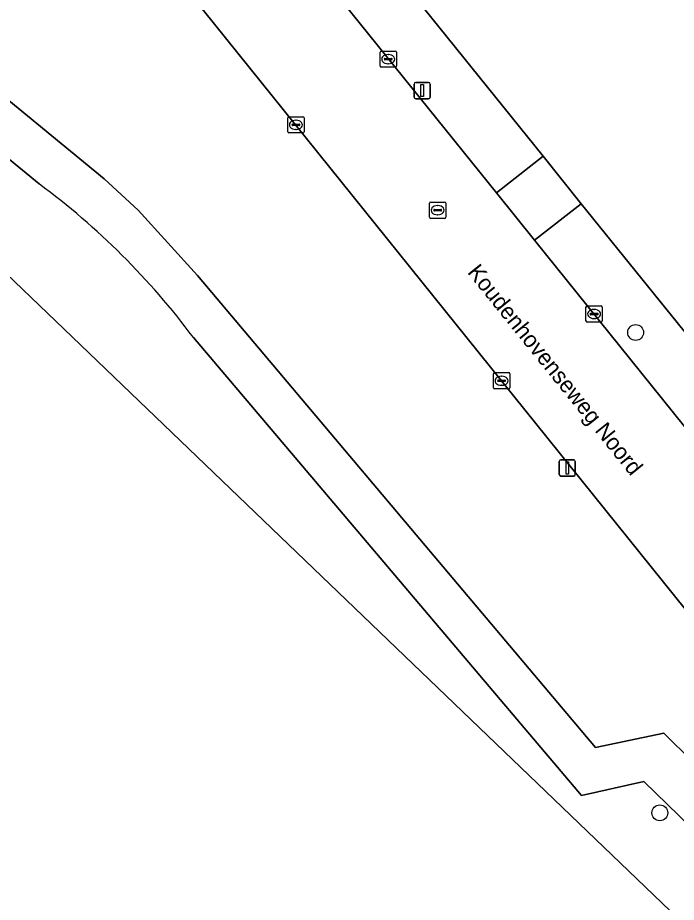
# Model space of a CAD drawing. Extents: x 162417 to 163722, y 384268 to 385417.
# Drawn here: x 163403.1 to 163443.6, y 384814.8 to 384869.2 of the extents above; entities that cross this region are included whole.
import ezdxf

# ---------------------------------------------------------------- set-up
doc = ezdxf.new("R2010")
doc.units = 0
for name, color, linetype in [('IMGEO_Berm_groen', 7, 'Continuous'), ('IMGEO_Boom', 7, 'Continuous'), ('IMGEO_Erf', 7, 'Continuous'), ('IMGEO_Kolk', 7, 'Continuous'), ('IMGEO_Lichtmast', 7, 'Continuous'), ('IMGEO_Loofbos', 7, 'Continuous'), ('IMGEO_Openbare_ruimte_label', 7, 'Continuous'), ('IMGEO_Rijbaan_lokaal_gesloten', 7, 'Continuous'), ('IMGEO_Rioolput', 7, 'Continuous'), ('IMGEO_Voetpad_open', 7, 'Continuous')]:
    doc.layers.add(name, color=color, linetype=linetype)

msp = doc.modelspace()

# ---------------------------------------------------------------- linework, layer by layer
at = {"layer": 'IMGEO_Berm_groen'}
for points in [[(163416.764, 384883.847), (163413.249, 384882.384), (163432.532, 384858.437), (163435.391, 384860.693)], [(163437.735, 384857.778), (163434.868, 384855.535), (163446.713, 384840.825), (163447.501, 384841.435), (163447.728, 384841.15), (163449.843, 384842.786), (163449.614, 384843.069)]]:
    msp.add_lwpolyline(points, close=True, dxfattribs=at)
at = {"layer": 'IMGEO_Boom'}
for centre in [(163441.083, 384849.86), (163442.567, 384820.322)]:
    msp.add_circle(centre, 0.489, dxfattribs=at)
at = {"layer": 'IMGEO_Erf'}
for points in [[(163565.372, 384794.06), (163550.928, 384821.281), (163500, 384915.752), (163498.731, 384918.106), (163416.764, 384883.847), (163435.391, 384860.693), (163437.735, 384857.778), (163449.614, 384843.069), (163449.843, 384842.786), (163451.746, 384840.437), (163452.011, 384840.109), (163461.716, 384828.124), (163463.926, 384825.396), (163473.971, 384812.925)], [(163478.968, 384778.944), (163452.807, 384811.328), (163449.552, 384814.496), (163444.744, 384812.832), (163371.736, 384882.911), (163368.168, 384880.503), (163366.653, 384879.471), (163363.837, 384877.552), (163359.249, 384874.08)]]:
    msp.add_lwpolyline(points, dxfattribs=at)
at = {"layer": 'IMGEO_Kolk'}
for p, q in [((163425.375, 384866.238), (163425.375, 384867.09)), ((163425.45, 384867.164), (163426.302, 384867.164)), ((163426.376, 384867.09), (163426.376, 384866.238)), ((163425.634, 384866.658), (163425.634, 384866.67)), ((163426.072, 384866.621), (163425.674, 384866.621)), ((163425.677, 384866.707), (163426.075, 384866.707)), ((163425.863, 384866.944), (163425.888, 384866.944)), ((163426.118, 384866.67), (163426.118, 384866.658)), ((163426.302, 384866.164), (163425.45, 384866.164)), ((163425.886, 384866.384), (163425.861, 384866.384)), ((163419.7, 384862.2), (163419.7, 384863.052)), ((163419.775, 384863.126), (163420.627, 384863.126)), ((163420.188, 384862.906), (163420.213, 384862.906)), ((163420.701, 384863.052), (163420.701, 384862.2)), ((163419.959, 384862.62), (163419.959, 384862.632)), ((163420.397, 384862.583), (163419.999, 384862.583)), ((163420.002, 384862.669), (163420.4, 384862.669)), ((163420.211, 384862.346), (163420.186, 384862.346)), ((163420.443, 384862.632), (163420.443, 384862.62)), ((163420.627, 384862.126), (163419.775, 384862.126)), ((163438.029, 384850.568), (163438.029, 384851.42)), ((163438.104, 384851.494), (163438.956, 384851.494)), ((163438.517, 384851.274), (163438.542, 384851.274)), ((163439.03, 384851.42), (163439.03, 384850.568)), ((163438.288, 384850.988), (163438.288, 384851)), ((163438.726, 384850.951), (163438.328, 384850.951)), ((163438.331, 384851.037), (163438.729, 384851.037)), ((163438.54, 384850.714), (163438.515, 384850.714)), ((163438.772, 384851), (163438.772, 384850.988)), ((163438.956, 384850.494), (163438.104, 384850.494)), ((163432.342, 384846.464), (163432.342, 384847.316)), ((163432.417, 384847.39), (163433.269, 384847.39)), ((163432.601, 384846.884), (163432.601, 384846.896)), ((163432.644, 384846.933), (163433.042, 384846.933)), ((163432.83, 384847.17), (163432.855, 384847.17)), ((163433.085, 384846.896), (163433.085, 384846.884)), ((163433.343, 384847.316), (163433.343, 384846.464)), ((163433.269, 384846.39), (163432.417, 384846.39)), ((163433.039, 384846.847), (163432.641, 384846.847)), ((163432.853, 384846.61), (163432.828, 384846.61))]:
    msp.add_line(p, q, dxfattribs=at)
for points in [[(163425.375, 384866.238), (163425.375, 384867.09)], [(163425.45, 384867.164), (163426.302, 384867.164)], [(163426.376, 384867.09), (163426.376, 384866.238)], [(163426.302, 384866.164), (163425.45, 384866.164)], [(163419.7, 384862.2), (163419.7, 384863.052)], [(163419.775, 384863.126), (163420.627, 384863.126)], [(163420.701, 384863.052), (163420.701, 384862.2)], [(163420.627, 384862.126), (163419.775, 384862.126)], [(163438.029, 384850.568), (163438.029, 384851.42)], [(163438.104, 384851.494), (163438.956, 384851.494)], [(163439.03, 384851.42), (163439.03, 384850.568)], [(163438.956, 384850.494), (163438.104, 384850.494)], [(163432.342, 384846.464), (163432.342, 384847.316)], [(163432.417, 384847.39), (163433.269, 384847.39)], [(163433.343, 384847.316), (163433.343, 384846.464)], [(163433.269, 384846.39), (163432.417, 384846.39)]]:
    msp.add_lwpolyline(points, dxfattribs=at)
for centre, radius, start, end in [((163425.452, 384867.088), 0.0765, 91.552, 178.448), ((163425.452, 384867.088), 0.0765, 91.552, 178.448), ((163426.3, 384867.088), 0.0765, 1.552, 88.448), ((163426.3, 384867.088), 0.0765, 1.552, 88.448), ((163425.674, 384866.667), 0.0403, 85.8775, 175.7526), ((163425.671, 384866.657), 0.0366, 178.938, 274.7102), ((163426.075, 384866.664), 0.043, 264.8664, 352.4533), ((163426.079, 384866.669), 0.0386, 1.7309, 96.639), ((163425.452, 384866.24), 0.0765, 181.552, 268.448), ((163425.452, 384866.24), 0.0765, 181.552, 268.448), ((163426.3, 384866.24), 0.0765, 271.552, 358.448), ((163426.3, 384866.24), 0.0765, 271.552, 358.448), ((163419.777, 384863.05), 0.0765, 91.552, 178.448), ((163419.777, 384863.05), 0.0765, 91.552, 178.448), ((163420.625, 384863.05), 0.0765, 1.552, 88.448), ((163420.625, 384863.05), 0.0765, 1.552, 88.448), ((163419.777, 384862.202), 0.0765, 181.552, 268.448), ((163419.777, 384862.202), 0.0765, 181.552, 268.448), ((163419.999, 384862.629), 0.0403, 85.8775, 175.7526), ((163419.996, 384862.619), 0.0366, 178.938, 274.7102), ((163420.4, 384862.626), 0.043, 264.8664, 352.4533), ((163420.404, 384862.631), 0.0386, 1.7309, 96.639), ((163420.625, 384862.202), 0.0765, 271.552, 358.448), ((163420.625, 384862.202), 0.0765, 271.552, 358.448), ((163438.106, 384851.418), 0.0765, 91.552, 178.448), ((163438.106, 384851.418), 0.0765, 91.552, 178.448), ((163438.954, 384851.418), 0.0765, 1.552, 88.448), ((163438.954, 384851.418), 0.0765, 1.552, 88.448), ((163438.328, 384850.997), 0.0403, 85.8775, 175.7526), ((163438.325, 384850.987), 0.0366, 178.938, 274.7102), ((163438.729, 384850.994), 0.043, 264.8664, 352.4533), ((163438.733, 384850.999), 0.0386, 1.7309, 96.639), ((163438.106, 384850.57), 0.0765, 181.552, 268.448), ((163438.106, 384850.57), 0.0765, 181.552, 268.448), ((163438.954, 384850.57), 0.0765, 271.552, 358.448), ((163438.954, 384850.57), 0.0765, 271.552, 358.448), ((163432.419, 384847.314), 0.0765, 91.552, 178.448), ((163432.419, 384847.314), 0.0765, 91.552, 178.448), ((163432.641, 384846.893), 0.0403, 85.8775, 175.7526), ((163433.046, 384846.895), 0.0386, 1.7309, 96.639), ((163433.267, 384847.314), 0.0765, 1.552, 88.448), ((163433.267, 384847.314), 0.0765, 1.552, 88.448), ((163432.419, 384846.466), 0.0765, 181.552, 268.448), ((163432.419, 384846.466), 0.0765, 181.552, 268.448), ((163432.638, 384846.883), 0.0366, 178.938, 274.7102), ((163433.042, 384846.89), 0.043, 264.8664, 352.4533), ((163433.267, 384846.466), 0.0765, 271.552, 358.448), ((163433.267, 384846.466), 0.0765, 271.552, 358.448)]:
    msp.add_arc(centre, radius, start, end, dxfattribs=at)
for centre, major_axis, ratio, start_param, end_param in [((163425.862, 384866.664), (-0.387, 0.002), 0.722429, 4.712389, 7.853982), ((163425.887, 384866.664), (-0.39, 0.002), 0.717154, 1.570796, 4.712389), ((163420.187, 384862.626), (-0.387, 0.002), 0.722429, 4.712389, 7.853982), ((163420.212, 384862.626), (-0.39, 0.002), 0.717154, 1.570796, 4.712389), ((163438.516, 384850.994), (-0.387, 0.002), 0.722429, 4.712389, 7.853982), ((163438.541, 384850.994), (-0.39, 0.002), 0.717154, 1.570796, 4.712389), ((163432.829, 384846.89), (-0.387, 0.002), 0.722429, 4.712389, 7.853982), ((163432.854, 384846.89), (-0.39, 0.002), 0.717154, 1.570796, 4.712389)]:
    msp.add_ellipse(centre, major_axis=major_axis, ratio=ratio, start_param=start_param, end_param=end_param, dxfattribs=at)
at = {"layer": 'IMGEO_Lichtmast'}
for p, q in [((163427.469, 384864.335), (163427.469, 384865.135)), ((163427.469, 384865.135), (163427.469, 384864.335)), ((163427.569, 384865.235), (163428.359, 384865.235)), ((163428.359, 384865.235), (163427.569, 384865.235)), ((163428.459, 384865.135), (163428.459, 384864.335)), ((163428.459, 384864.335), (163428.459, 384865.135)), ((163428.359, 384864.235), (163427.569, 384864.235)), ((163427.569, 384864.235), (163428.359, 384864.235)), ((163436.484, 384842.029), (163437.274, 384842.029)), ((163437.274, 384842.029), (163436.484, 384842.029)), ((163436.384, 384841.129), (163436.384, 384841.929)), ((163436.384, 384841.929), (163436.384, 384841.129)), ((163437.374, 384841.929), (163437.374, 384841.129)), ((163437.374, 384841.129), (163437.374, 384841.929)), ((163437.274, 384841.029), (163436.484, 384841.029)), ((163436.484, 384841.029), (163437.274, 384841.029))]:
    msp.add_line(p, q, dxfattribs=at)
for points in [[(163427.889, 384865.11), (163428.039, 384865.11), (163428.039, 384864.36), (163427.889, 384864.36), (163427.889, 384865.11)], [(163436.804, 384841.904), (163436.954, 384841.904), (163436.954, 384841.154), (163436.804, 384841.154), (163436.804, 384841.904)]]:
    msp.add_lwpolyline(points, dxfattribs=at)
for centre, start, end in [((163427.569, 384865.135), 90, 180), ((163427.569, 384865.135), 90, 180), ((163428.359, 384865.135), 0, 90), ((163428.359, 384865.135), 360, 90), ((163427.569, 384864.335), 180, 270), ((163427.569, 384864.335), 180, 270), ((163428.359, 384864.335), 270, 0), ((163428.359, 384864.335), 270, 0), ((163436.484, 384841.929), 90, 180), ((163436.484, 384841.929), 90, 180), ((163437.274, 384841.929), 0, 90), ((163437.274, 384841.929), 360, 90), ((163436.484, 384841.129), 180, 270), ((163436.484, 384841.129), 180, 270), ((163437.274, 384841.129), 270, 0), ((163437.274, 384841.129), 270, 0)]:
    msp.add_arc(centre, 0.1, start, end, dxfattribs=at)
at = {"layer": 'IMGEO_Loofbos'}
for points in [[(163404.422, 384858.994), (163383.225, 384876.4), (163378.166, 384887.357), (163371.736, 384882.911), (163444.744, 384812.832), (163449.552, 384814.496), (163441.59, 384822.244), (163437.759, 384821.38), (163413.902, 384849.546)], [(163392.196, 384872.647), (163408.421, 384859.297), (163410.514, 384857.379), (163414.147, 384853.364), (163438.619, 384824.336), (163442.822, 384825.228), (163444.598, 384823.469), (163448.899, 384826.989), (163448.546, 384827.421), (163446.26, 384830.213), (163406.766, 384879.335), (163392.734, 384873.707), (163392.106, 384873.165)]]:
    msp.add_lwpolyline(points, dxfattribs=at)
msp.add_arc((163377.171, 384822.171), 45.81, 36.6968, 53.4969, dxfattribs=at)
at = {"layer": 'IMGEO_Rijbaan_lokaal_gesloten'}
msp.add_lwpolyline([(163406.766, 384879.335), (163446.26, 384830.213), (163448.546, 384827.421), (163453.877, 384831.928), (163449.136, 384837.816), (163446.713, 384840.825), (163434.868, 384855.535), (163432.532, 384858.437), (163413.249, 384882.384)], dxfattribs=at)
at = {"layer": 'IMGEO_Rioolput'}
for p, q in [((163428.413, 384856.952), (163428.413, 384857.804)), ((163428.488, 384857.878), (163429.34, 384857.878)), ((163429.414, 384857.804), (163429.414, 384856.952)), ((163428.672, 384857.372), (163428.672, 384857.384)), ((163429.11, 384857.335), (163428.712, 384857.335)), ((163428.715, 384857.421), (163429.113, 384857.421)), ((163428.901, 384857.658), (163428.926, 384857.658)), ((163429.156, 384857.384), (163429.156, 384857.372)), ((163429.34, 384856.878), (163428.488, 384856.878)), ((163428.924, 384857.098), (163428.899, 384857.098))]:
    msp.add_line(p, q, dxfattribs=at)
for points in [[(163428.413, 384856.952), (163428.413, 384857.804)], [(163428.488, 384857.878), (163429.34, 384857.878)], [(163429.414, 384857.804), (163429.414, 384856.952)], [(163429.34, 384856.878), (163428.488, 384856.878)]]:
    msp.add_lwpolyline(points, dxfattribs=at)
for centre, radius, start, end in [((163428.49, 384857.802), 0.0765, 91.552, 178.448), ((163428.49, 384857.802), 0.0765, 91.552, 178.448), ((163429.338, 384857.802), 0.0765, 1.552, 88.448), ((163429.338, 384857.802), 0.0765, 1.552, 88.448), ((163428.712, 384857.381), 0.0403, 85.8775, 175.7526), ((163428.709, 384857.371), 0.0366, 178.938, 274.7102), ((163429.113, 384857.378), 0.043, 264.8664, 352.4533), ((163429.117, 384857.383), 0.0386, 1.7309, 96.639), ((163428.49, 384856.954), 0.0765, 181.552, 268.448), ((163428.49, 384856.954), 0.0765, 181.552, 268.448), ((163429.338, 384856.954), 0.0765, 271.552, 358.448), ((163429.338, 384856.954), 0.0765, 271.552, 358.448)]:
    msp.add_arc(centre, radius, start, end, dxfattribs=at)
for centre, major_axis, ratio, start_param, end_param in [((163428.9, 384857.378), (-0.387, 0.002), 0.722429, 4.712389, 7.853982), ((163428.925, 384857.378), (-0.39, 0.002), 0.717154, 1.570796, 4.712389)]:
    msp.add_ellipse(centre, major_axis=major_axis, ratio=ratio, start_param=start_param, end_param=end_param, dxfattribs=at)
at = {"layer": 'IMGEO_Voetpad_open'}
for points in [[(163414.147, 384853.364), (163410.514, 384857.379), (163408.421, 384859.297), (163392.196, 384872.647), (163388.512, 384875.738), (163385.472, 384878.291), (163380.909, 384888.238), (163379.128, 384892.265), (163374.727, 384900.875), (163364.022, 384920.643), (163344.699, 384957.814)], [(163347.204, 384946.37), (163360.118, 384921.532), (163369.878, 384904.051), (163377.046, 384890.814), (163378.166, 384887.357), (163383.225, 384876.4), (163404.422, 384858.994)], [(163502.447, 384756.771), (163501.034, 384756.293), (163498.788, 384759.203), (163472.091, 384792.3), (163470.199, 384794.668), (163457.83, 384809.947), (163455.351, 384812.817), (163444.598, 384823.469), (163442.822, 384825.228), (163438.619, 384824.336), (163414.147, 384853.364)], [(163413.902, 384849.546), (163437.759, 384821.38), (163441.59, 384822.244), (163449.552, 384814.496), (163452.807, 384811.328), (163478.968, 384778.944)]]:
    msp.add_lwpolyline(points, dxfattribs=at)
msp.add_lwpolyline([(163437.735, 384857.778), (163435.391, 384860.693), (163432.532, 384858.437), (163434.868, 384855.535)], close=True, dxfattribs=at)
msp.add_arc((163377.171, 384822.171), 45.81, 36.6968, 53.4969, dxfattribs=at)

# ---------------------------------------------------------------- texts
at = {"layer": 'IMGEO_Openbare_ruimte_label'}
msp.add_text('Koudenhovenseweg Noord', height=1, rotation=308.8298, dxfattribs=at).set_placement((163430.698, 384853.549))

doc.saveas('drawing.dxf')
